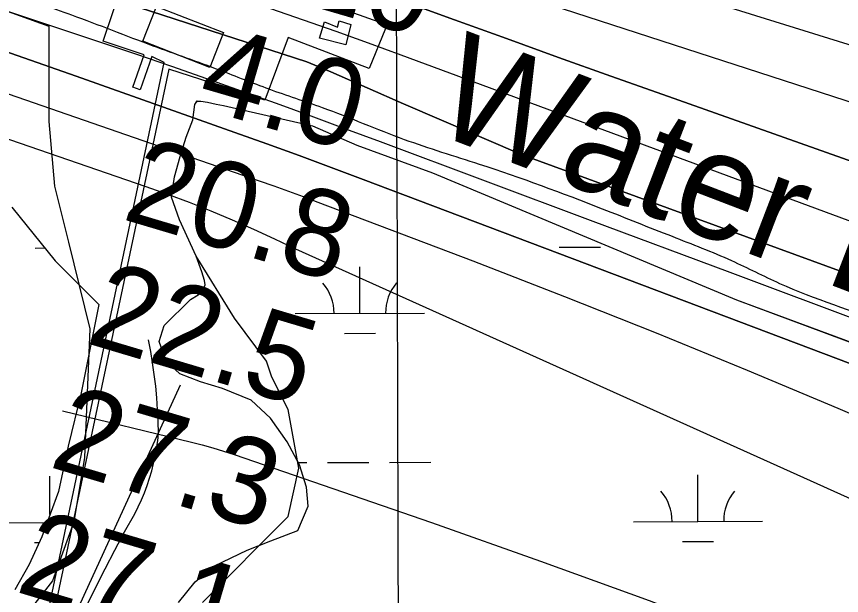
# Model space of a CAD drawing. Extents: x 3361039 to 3398939, y 576572 to 602007.
# Drawn here: x 3391205 to 3391844, y 584508 to 584956 of the extents above; entities that cross this region are included whole.
import ezdxf

# ---------------------------------------------------------------- set-up
doc = ezdxf.new("R2010")
doc.units = 0
for name, color, linetype in [('V-BLDG-OTLN', 7, 'Continuous'), ('V-CHAN-DOCK', 7, 'Continuous'), ('V-GRID-MAJR', 7, 'Continuous'), ('V-RIVR-EDGE', 7, 'Continuous'), ('V-RIVR-IDEN', 7, 'Continuous'), ('V-RIVR-RANG', 7, 'Continuous'), ('V-ROAD-CNTR', 7, 'Continuous'), ('V-SITE-VEGE', 7, 'Continuous'), ('V-TOPO-DPTH', 7, 'Continuous'), ('V-TOPO-MAJR', 7, 'Continuous'), ('V-TOPO-MINR', 7, 'Continuous'), ('V-TOPO-WATR', 7, 'Continuous'), ('V-WETL-SWMP', 7, 'Continuous')]:
    doc.layers.add(name, color=color, linetype=linetype)

msp = doc.modelspace()

# ---------------------------------------------------------------- linework, layer by layer
at = {"layer": 'V-BLDG-OTLN'}
for points in [[(3391313.48, 584963.85), (3391365.34, 584943.77), (3391354.9, 584916.81), (3391302.75, 584937)], [(3391439.85, 584939.35), (3391443.51, 584951.96), (3391453.76, 584948.03), (3391454.84, 584952.87), (3391463.93, 584949.99), (3391460.09, 584934.15)]]:
    msp.add_lwpolyline(points, close=True, dxfattribs=at)
at = {"layer": 'V-CHAN-DOCK'}
msp.add_lwpolyline([(3391216.09, 584431.75), (3391319.37, 584920.56), (3391309.86, 584925.21), (3391300.77, 584899.42), (3391295.21, 584901.54), (3391303.99, 584926.45), (3391272.04, 584937.06), (3391287.95, 584983.96), (3391295.12, 584980.8), (3391307.68, 585015.67), (3391489.23, 584950.77), (3391490.81, 584946.78), (3391478.14, 584915.88), (3391415.45, 584939.89), (3391397.31, 584891.39), (3391322.99, 584915.37), (3391227.75, 584465.31), (3391220.49, 584430.82), (3391216.09, 584431.75)], dxfattribs=at)
at = {"layer": 'V-GRID-MAJR'}
msp.add_spline([(3391508.24, 582029.76), (3391489.73, 588088.95), (3391471.22, 594150.08), (3391452.71, 600211.22), (3391452.7, 600213.13)], degree=3, dxfattribs=at)
at = {"layer": 'V-RIVR-EDGE'}
msp.add_spline([(3387368.61, 585771.04), (3387388.99, 585767.6), (3387407.26, 585766.09), (3387418.22, 585761.68), (3387425.51, 585756.54), (3387441.59, 585752.85), (3387452.55, 585751.36), (3387462.06, 585753.9), (3387477.43, 585758.24), (3387482.91, 585759.33), (3387491.69, 585759.31), (3387502.28, 585758.18), (3387510.32, 585756.34), (3387521.64, 585753.02), (3387530.05, 585752.27), (3387538.46, 585752.24), (3387549.79, 585752.22), (3387558.94, 585755.48), (3387571.37, 585756.92), (3387583.43, 585757.25), (3387598.42, 585756.12), (3387629.84, 585749.46), (3387659.8, 585743.54), (3387703.28, 585736.85), (3387727.4, 585734.23), (3387739.1, 585733.47), (3387750.8, 585734.17), (3387753.72, 585731.61), (3387763.2, 585723.91), (3387774.52, 585720.59), (3387790.61, 585719.82), (3387800.12, 585721.62), (3387814, 585720.13), (3387824.6, 585720.1), (3387847.25, 585714.2), (3387884.16, 585709.35), (3387930.2, 585702.66), (3387980.65, 585701.07), (3388035.1, 585696.55), (3388076.04, 585694.62), (3388096.87, 585693.84), (3388120.26, 585690.49), (3388145.1, 585685.31), (3388171.78, 585682.32), (3388198.82, 585676.77), (3388222.56, 585669.4), (3388245.57, 585660.57), (3388260.91, 585655.42), (3388279.55, 585655.37), (3388291.26, 585658.26), (3388298.95, 585663.73), (3388299.32, 585666.29), (3388298.96, 585670.67), (3388290.56, 585674.35), (3388291.67, 585677.27), (3388293.86, 585678.36), (3388303, 585677.61), (3388318.72, 585676.47), (3388334.06, 585672.78), (3388354.14, 585663.59), (3388357.06, 585659.93), (3388363.27, 585658.09), (3388368.39, 585658.07), (3388370.95, 585660.99), (3388375.34, 585662.08), (3388379, 585661.34), (3388383.01, 585659.13), (3388383.73, 585654.38), (3388384.08, 585649.26), (3388389.93, 585647.42), (3388406, 585642.26), (3388468.86, 585637.72), (3388491.52, 585635.84), (3388534.64, 585628.42), (3388578.12, 585619.17), (3388610.64, 585613.61), (3388635.85, 585612.08), (3388727.94, 585599.43), (3388768.5, 585591.65), (3388822.57, 585580.92), (3388864.95, 585570.58), (3388906.6, 585562.8), (3388924.14, 585559.46), (3388938.77, 585561.99), (3388961.44, 585563.39), (3388974.22, 585560.07), (3389007.47, 585553.41), (3389018.81, 585554.48), (3389027.22, 585555.92), (3389037.09, 585555.89), (3389051.7, 585553.67), (3389061.21, 585553.28), (3389081.31, 585552.13), (3389098.12, 585550.99), (3389120.42, 585548.74), (3389143.44, 585546.49), (3389160.24, 585542.06), (3389200.8, 585534.65), (3389222.35, 585525.1), (3389247.19, 585519.19), (3389280.43, 585509.6), (3389307.45, 585497.83), (3389334.48, 585487.17), (3389349.45, 585483.11), (3389361.52, 585483.08), (3389382.71, 585479.01), (3389396.96, 585476.78), (3389416.68, 585468.69), (3389441.88, 585458.39), (3389464.89, 585451.39), (3389479.5, 585449.16), (3389506.18, 585446.17), (3389533.23, 585447.2), (3389558.45, 585444.21), (3389577.81, 585437.95), (3389603.38, 585431.3), (3389618.72, 585425.05), (3389639.16, 585415.13), (3389657.8, 585410.33), (3389693.24, 585404.76), (3389768.86, 585383.01), (3389806.48, 585373.05), (3389854.34, 585362.33), (3389881.75, 585358.6), (3389913.91, 585354.5), (3389953.74, 585349.29), (3390008.19, 585341.84), (3390037.78, 585336.28), (3390074.32, 585327.79), (3390128.02, 585312.67), (3390164.54, 585301.61), (3390200.7, 585289.82), (3390292.74, 585255.6), (3390327.06, 585241.26), (3390360.67, 585231.67), (3390404.51, 585220.96), (3390454.94, 585214.26), (3390483.08, 585210.53), (3390491.85, 585209.41), (3390494.4, 585207.21), (3390501.33, 585200.98), (3390507.91, 585200.6), (3390527.27, 585196.17), (3390545.91, 585195.02), (3390557.61, 585194.26), (3390574.41, 585189.83), (3390605.46, 585179.52), (3390698.6, 585148.22), (3390763.25, 585126.86), (3390811.09, 585111.02), (3390852.37, 585097.76), (3390900.95, 585081.56), (3390948.06, 585063.53), (3390993.71, 585048.43), (3391036.81, 585031.87), (3391070.77, 585020.09), (3391140.54, 584997.62), (3391201.53, 584974.07), (3391247.54, 584957.51), (3391310.73, 584933.59), (3391362.22, 584914.82), (3391400.57, 584900.1), (3391441.84, 584885.75), (3391505.38, 584861.1), (3391563.46, 584841.95), (3391658.78, 584807.35), (3391712.83, 584786.01), (3391758.84, 584767.26), (3391796.08, 584749.62), (3391880.45, 584718.34), (3391926.83, 584701.41), (3391969.2, 584685.22), (3392003.88, 584666.85), (3392040.03, 584650.32), (3392077.64, 584635.97), (3392135.71, 584613.16), (3392164.91, 584598.1), (3392195.95, 584583.77), (3392224.82, 584578.21), (3392263.54, 584567.88), (3392290.57, 584559.77), (3392322.7, 584546.53), (3392396.46, 584512.72), (3392439.92, 584496.16), (3392471.69, 584484.75), (3392502.01, 584473.34), (3392510.77, 584467.47), (3392535.24, 584458.27), (3392606.09, 584432.88), (3392632.38, 584421.48), (3392666.71, 584406.77), (3392715.64, 584386.91), (3392777.36, 584364.83), (3392827.04, 584348.25), (3392863.56, 584335.37), (3392897.89, 584321.76), (3392928.56, 584307.79), (3392965.45, 584294.91), (3393010.01, 584279.08), (3393054.56, 584263.25), (3393092.54, 584248.53), (3393195.16, 584206.61), (3393234.23, 584187.87), (3393264.53, 584173.54), (3393294.11, 584162.13), (3393336.85, 584147.4), (3393374.47, 584136.34), (3393402.23, 584127.5), (3393414.27, 584119.8), (3393435.45, 584109.14), (3393459.18, 584098.12), (3393478.9, 584087.47), (3393513.6, 584076.42), (3393541.72, 584067.21), (3393588.1, 584047.35), (3393643.25, 584028.94), (3393668.44, 584018.28), (3393699.85, 584005.04), (3393737.1, 583991.79), (3393781.66, 583975.96), (3393884.66, 583943.17), (3393927.03, 583928.81), (3393981.08, 583908.2), (3394043.9, 583885.38), (3394095.77, 583868.08), (3394154.93, 583847.09), (3394200.22, 583830.53), (3394246.97, 583816.16), (3394293, 583801.42), (3394349.61, 583781.18), (3394409.13, 583754.71), (3394451.84, 583730.48), (3394470.45, 583720.2), (3394481.77, 583715.42), (3394494.2, 583713.56), (3394502.59, 583708.06), (3394507.32, 583700.37), (3394511.34, 583697.8), (3394522.66, 583692.29), (3394557.34, 583675.75), (3394600.44, 583659.93), (3394658.14, 583638.95), (3394704.53, 583623.48), (3394760.42, 583607.62), (3394823.98, 583588.82), (3394867.8, 583570.8), (3394925.86, 583546.9), (3394972.24, 583528.87), (3394995.62, 583520.04), (3395064.67, 583504.15), (3395088.42, 583499.34), (3395120.2, 583491.59), (3395149.05, 583480.55), (3395173.17, 583476.83), (3395201.3, 583471.28), (3395236.37, 583459.86), (3395256.82, 583451.77), (3395280.93, 583445.5), (3395300.3, 583445.08), (3395316.74, 583440.65), (3395324.4, 583433.32), (3395335.35, 583425.99), (3395353.6, 583417.9), (3395398.9, 583403.9), (3395426.3, 583397.25), (3395442, 583391), (3395455.87, 583383.28), (3395475.96, 583377.75), (3395495.68, 583369.3), (3395511.03, 583368.16), (3395530.4, 583365.92), (3395550.49, 583361.85), (3395654.61, 583334.91), (3395704.66, 583322.35), (3395743.73, 583306.9), (3395765.27, 583295.52), (3395788.28, 583286.32), (3395816.41, 583278.94), (3395861.72, 583270.79), (3395916.16, 583261.52), (3395960.74, 583252.63), (3396008.6, 583242.64), (3396060.84, 583230.45), (3396093.36, 583222.33), (3396135.36, 583208.7), (3396170.06, 583199.84), (3396204.41, 583191.35), (3396254.82, 583177.33), (3396301.21, 583165.89), (3396364.42, 583152.94), (3396399.13, 583144.44), (3396426.89, 583138.53), (3396463.07, 583132.95), (3396489.75, 583132.89), (3396523.38, 583130.24), (3396607.78, 583113.95), (3396670.26, 583102.1), (3396708.26, 583095.43), (3396742.97, 583089.49), (3396775.14, 583083.89)], degree=3, dxfattribs=at)
at = {"layer": 'V-ROAD-CNTR'}
for points in [[(3391259.23, 584499.82), (3391266.34, 584514.3), (3391273.64, 584528.68), (3391281.11, 584542.96), (3391288.78, 584557.15), (3391296.62, 584571.24), (3391299.3, 584576.55), (3391301.79, 584581.96), (3391304.08, 584587.45), (3391306.17, 584593.02), (3391308.05, 584598.66), (3391309.73, 584604.36), (3391311.21, 584610.13), (3391312.48, 584615.94), (3391313.53, 584621.79), (3391314.37, 584627.68), (3391315, 584633.59), (3391314.79, 584642.69), (3391314.36, 584651.78), (3391313.71, 584660.85), (3391312.85, 584669.91), (3391311.77, 584678.94), (3391310.47, 584687.95), (3391308.96, 584696.92), (3391307.23, 584705.86)], [(3391105.77, 584199.79), (3391198.24, 584379.28), (3391332.08, 584670.96)]]:
    msp.add_lwpolyline(points, dxfattribs=at)
at = {"layer": 'V-SITE-VEGE'}
for p, q in [((3391343.18, 584887.97), (3391344.92, 584890.78)), ((3391344.92, 584890.78), (3391347.89, 584890.62)), ((3391347.89, 584890.62), (3391352.85, 584889.97)), ((3391352.85, 584889.97), (3391359.6, 584888.32)), ((3391341.56, 584876.31), (3391343.18, 584887.97)), ((3391359.6, 584888.32), (3391365.3, 584887.41)), ((3391365.3, 584887.41), (3391375.51, 584884.97)), ((3391375.51, 584884.97), (3391434.23, 584871.52)), ((3391336.5, 584862.69), (3391341.56, 584876.31)), ((3391434.23, 584871.52), (3391468.65, 584856.58)), ((3391331.68, 584847.76), (3391336.5, 584862.69)), ((3391468.65, 584856.58), (3391527.38, 584835.2)), ((3391327.44, 584831.99), (3391331.68, 584847.76)), ((3391527.38, 584835.2), (3391762.8, 584736.93)), ((3391325.19, 584816.31), (3391327.44, 584831.99)), ((3391331.32, 584798.82), (3391325.19, 584816.31)), ((3391344.21, 584770.77), (3391331.32, 584798.82)), ((3391373.86, 584722.63), (3391344.21, 584770.77)), ((3391762.8, 584736.93), (3391959.52, 584663.64)), ((3391398.75, 584689.43), (3391373.86, 584722.63)), ((3391402.9, 584676.97), (3391398.75, 584689.43)), ((3391415.34, 584652.06), (3391402.9, 584676.97)), ((3391423.64, 584606.4), (3391415.34, 584652.06)), ((3391415.34, 584569.04), (3391423.64, 584606.4)), ((3391348.97, 584502.61), (3391415.34, 584569.04))]:
    msp.add_line(p, q, dxfattribs=at)
msp.add_lwpolyline([(3391127.99, 584985.74), (3391230.13, 584948.79), (3391230.13, 584874.88), (3391234.47, 584824.88), (3391245.34, 584781.41), (3391261.86, 584714.33), (3391257.71, 584614.7), (3391249.42, 584564.89), (3391232.82, 584519.22), (3391203.79, 584481.86)], dxfattribs=at)
at = {"layer": 'V-TOPO-DPTH'}
for points in [[(3390678.68, 585282.14), (3390852.22, 585234.68), (3390949.88, 585207.56), (3391047.4, 585179.91), (3391144.68, 585151.49), (3391241.82, 585122.55), (3391423.59, 585067.59), (3391453.42, 585058.52), (3391483.22, 585049.38), (3391512.99, 585040.14), (3391542.75, 585030.83), (3391694.3, 584983.11), (3391799.86, 584950.05), (3391905.48, 584917.2), (3392011.21, 584884.69), (3392117.01, 584852.38), (3392327.21, 584788.55), (3392352.54, 584780.89), (3392377.87, 584773.24), (3392403.21, 584765.64), (3392428.56, 584758.07), (3392783.55, 584652.29), (3392834.95, 584637), (3392886.36, 584621.74)], [(3390678.68, 585282.14), (3390852.22, 585234.68), (3390949.88, 585207.56), (3391047.4, 585179.91), (3391144.68, 585151.49), (3391241.82, 585122.55), (3391423.59, 585067.59), (3391453.42, 585058.52), (3391483.22, 585049.38), (3391512.99, 585040.14), (3391542.75, 585030.83), (3391694.3, 584983.11), (3391799.86, 584950.05), (3391905.48, 584917.2), (3392011.21, 584884.69), (3392117.01, 584852.38), (3392327.21, 584788.55), (3392352.54, 584780.89), (3392377.87, 584773.24), (3392403.21, 584765.64), (3392428.56, 584758.07), (3392783.55, 584652.29), (3392834.95, 584637), (3392886.36, 584621.74)], [(3393031.47, 584404.12), (3392383, 584655.56), (3392365.1, 584662.05), (3392347.18, 584668.51), (3392329.25, 584674.92), (3392311.3, 584681.3), (3391705.74, 584895.71), (3391665.33, 584910.08), (3391624.94, 584924.53), (3391584.59, 584939.09), (3391544.27, 584953.73), (3391492.33, 584972.68), (3391477.98, 584977.85), (3391463.61, 584982.94), (3391449.2, 584987.93), (3391434.77, 584992.85), (3391420.29, 584997.64), (3391405.79, 585002.33), (3391391.23, 585006.88), (3391376.65, 585011.32), (3390699.4, 585214.13), (3390668.65, 585223.2)], [(3390668.65, 585223.2), (3390699.4, 585214.13), (3391376.65, 585011.32), (3391391.23, 585006.88), (3391405.79, 585002.33), (3391420.29, 584997.64), (3391434.77, 584992.85), (3391449.2, 584987.93), (3391463.61, 584982.94), (3391477.98, 584977.85), (3391492.33, 584972.68), (3391544.27, 584953.73), (3391584.59, 584939.09), (3391624.94, 584924.53), (3391665.33, 584910.08), (3391705.74, 584895.71), (3392311.3, 584681.3), (3392329.25, 584674.92), (3392347.18, 584668.51), (3392365.1, 584662.05), (3392383, 584655.56), (3393031.47, 584404.12)], [(3392928.64, 584331.59), (3392676.04, 584440.35), (3392339.21, 584576.56), (3392323.05, 584583.41), (3392305.19, 584590.26), (3391596.6, 584849.14), (3391504.75, 584888.53), (3391448.62, 584913.36), (3391429.91, 584921.07), (3391160.22, 585008.58), (3390745.08, 585150.09), (3390651.51, 585182.68)], [(3390651.51, 585182.68), (3390745.08, 585150.09), (3391160.22, 585008.58), (3391429.91, 584921.07), (3391448.62, 584913.36), (3391504.75, 584888.53), (3391596.6, 584849.14), (3392305.19, 584590.26), (3392323.05, 584583.41), (3392339.21, 584576.56), (3392676.04, 584440.35), (3392928.64, 584331.59)], [(3392986.66, 584240.65), (3392333.62, 584495.22), (3392300.45, 584508.97), (3392267.28, 584522.7), (3392234.1, 584536.42), (3392180.19, 584558.7), (3392119.94, 584583.28), (3392059.55, 584607.49), (3391998.94, 584631.14), (3391938.19, 584654.43), (3391473.68, 584830.06), (3391448.83, 584839.36), (3391423.95, 584848.55), (3391399, 584857.59), (3391374.02, 584866.51), (3391251.26, 584909.91), (3391164.74, 584940.09), (3391078.06, 584969.79), (3390991.13, 584998.77), (3390904.05, 585027.26), (3390649.76, 585109.28)]]:
    msp.add_lwpolyline(points, dxfattribs=at)
at = {"layer": 'V-TOPO-MAJR'}
msp.add_lwpolyline([(3391240.56, 584650.94), (3391340.55, 584626.71), (3391348.89, 584624.56), (3391357.2, 584622.26), (3391365.43, 584619.72), (3391373.62, 584617.03), (3391526.6, 584564.37), (3391611.01, 584534.59), (3391695.09, 584503.96), (3391778.7, 584472.05), (3391862, 584439.28), (3392196.65, 584304.67), (3392216.24, 584296.6), (3392235.75, 584288.32), (3392255.12, 584279.73), (3392274.4, 584270.93), (3392353.62, 584233.98), (3392377.35, 584222.39), (3392400.8, 584210.25), (3392423.79, 584197.29), (3392446.49, 584183.78), (3392458.11, 584176.09)], dxfattribs=at)
at = {"layer": 'V-TOPO-MINR'}
for points in [[(3390678.68, 585282.14), (3390852.22, 585234.68), (3390949.88, 585207.56), (3391047.4, 585179.91), (3391144.68, 585151.49), (3391241.82, 585122.55), (3391423.59, 585067.59), (3391453.42, 585058.52), (3391483.22, 585049.38), (3391512.99, 585040.14), (3391542.75, 585030.83), (3391694.3, 584983.11), (3391799.86, 584950.05), (3391905.48, 584917.2), (3392011.21, 584884.69), (3392117.01, 584852.38), (3392327.21, 584788.55), (3392352.54, 584780.89), (3392377.87, 584773.24), (3392403.21, 584765.64), (3392428.56, 584758.07), (3392783.55, 584652.29), (3392834.95, 584637), (3392886.36, 584621.74)], [(3390656.01, 585264.91), (3391449.41, 585019.99), (3391460.93, 585016.41), (3391472.43, 585012.8), (3391483.92, 585009.14), (3391495.39, 585005.44), (3392170.03, 584786.77), (3392202.26, 584776.27), (3392234.47, 584765.71), (3392266.65, 584755.06), (3392298.81, 584744.35), (3392358, 584724.53), (3392360.55, 584723.68), (3392363.1, 584722.83), (3392365.65, 584721.97), (3392368.2, 584721.12), (3392655.39, 584625.04), (3392725.16, 584601.76), (3392794.96, 584578.58), (3392864.81, 584555.51)], [(3390668.65, 585223.2), (3390699.4, 585214.13), (3391376.65, 585011.32), (3391391.23, 585006.88), (3391405.79, 585002.33), (3391420.29, 584997.64), (3391434.77, 584992.85), (3391449.2, 584987.93), (3391463.61, 584982.94), (3391477.98, 584977.85), (3391492.33, 584972.68), (3391544.27, 584953.73), (3391584.59, 584939.09), (3391624.94, 584924.53), (3391665.33, 584910.08), (3391705.74, 584895.71), (3392311.3, 584681.3), (3392329.25, 584674.92), (3392347.18, 584668.51), (3392365.1, 584662.05), (3392383, 584655.56), (3393031.47, 584404.12)], [(3390668.48, 585197.97), (3390896.04, 585128.73), (3390989.33, 585099.82), (3391082.4, 585070.25), (3391175.15, 585039.71), (3391267.7, 585008.51), (3391401.86, 584962.51), (3391427.13, 584953.74), (3391452.37, 584944.86), (3391477.53, 584935.79), (3391502.66, 584926.6), (3392077.3, 584714.19), (3392119.9, 584698.41), (3392162.49, 584682.6), (3392205.05, 584666.75), (3392247.6, 584650.85), (3392251.72, 584649.31), (3392292.19, 584634.12), (3392332.63, 584618.86), (3392373.03, 584603.49), (3392413.4, 584588.07), (3393024.79, 584355.28)], [(3390691.29, 585129.56), (3391270.75, 584936.12), (3391297.9, 584926.96), (3391325.02, 584917.68), (3391352.08, 584908.24), (3391379.09, 584898.69), (3391406.06, 584888.99), (3391433, 584879.22), (3391459.9, 584869.33), (3391486.77, 584859.36), (3391649.49, 584798.61), (3391757.69, 584758.2), (3391865.89, 584717.77)], [(3390649.76, 585109.28), (3390904.05, 585027.26), (3390991.13, 584998.77), (3391078.06, 584969.79), (3391164.74, 584940.09), (3391251.26, 584909.91), (3391374.02, 584866.51), (3391399, 584857.59), (3391423.95, 584848.55), (3391448.83, 584839.36), (3391473.68, 584830.06), (3391938.19, 584654.43), (3391998.94, 584631.14), (3392059.55, 584607.49), (3392119.94, 584583.28), (3392180.19, 584558.7), (3392234.1, 584536.42), (3392267.28, 584522.7), (3392300.45, 584508.97), (3392333.62, 584495.22), (3392986.66, 584240.65)], [(3390617.24, 585092.88), (3390711.53, 585062.51), (3390770.43, 585043.33), (3390829.25, 585023.88), (3390887.93, 585004.03), (3390946.53, 584983.93), (3391393.03, 584829.05), (3391404.43, 584825.03), (3391415.81, 584820.96), (3391427.16, 584816.78), (3391438.48, 584812.54), (3391558.47, 584767.01), (3391629.59, 584739.51), (3391700.47, 584711.42), (3391770.99, 584682.45), (3391841.27, 584652.89), (3392226.21, 584488.13), (3392256.54, 584475.3), (3393034.35, 584188.93)], [(3390612.83, 585063.35), (3391305.14, 584824.7), (3391322.05, 584818.65), (3391338.86, 584812.35), (3391355.52, 584805.66), (3391372.08, 584798.71), (3391388.51, 584791.45), (3391404.86, 584784.02), (3391421.09, 584776.34), (3392242.13, 584407), (3392267.57, 584396.72), (3392293, 584386.42), (3392910.01, 584097.13)]]:
    msp.add_lwpolyline(points, dxfattribs=at)
at = {"layer": 'V-TOPO-WATR'}
msp.add_lwpolyline([(3392928.64, 584331.59), (3392676.04, 584440.35), (3392339.21, 584576.56), (3392323.05, 584583.41), (3392305.19, 584590.26), (3391596.6, 584849.14), (3391504.75, 584888.53), (3391448.62, 584913.36), (3391429.91, 584921.07), (3391160.22, 585008.58), (3390745.08, 585150.09), (3390651.51, 585182.68)], dxfattribs=at)
at = {"layer": 'V-WETL-SWMP'}
for p, q in [((3391343.17, 584887.97), (3391344.92, 584890.77)), ((3391344.92, 584890.77), (3391347.89, 584890.62)), ((3391347.89, 584890.62), (3391352.85, 584889.97)), ((3391352.85, 584889.97), (3391359.6, 584888.32)), ((3391341.56, 584876.31), (3391343.17, 584887.97)), ((3391359.6, 584888.32), (3391365.3, 584887.4)), ((3391365.3, 584887.4), (3391375.51, 584884.96)), ((3391375.51, 584884.96), (3391434.23, 584871.52)), ((3391336.5, 584862.69), (3391341.56, 584876.31)), ((3391434.23, 584871.52), (3391468.65, 584856.58)), ((3391331.68, 584847.76), (3391336.5, 584862.69)), ((3391468.65, 584856.58), (3391527.38, 584835.2)), ((3391327.44, 584831.99), (3391331.68, 584847.76)), ((3391527.38, 584835.2), (3391762.8, 584736.92)), ((3391325.19, 584816.31), (3391327.44, 584831.99)), ((3391331.32, 584798.82), (3391325.19, 584816.31)), ((3391339.84, 584780.17), (3391331.32, 584798.82)), ((3391219.4, 584776.97), (3391226.91, 584776.99)), ((3391344.21, 584770.78), (3391339.84, 584780.17)), ((3391625.41, 584777.54), (3391657.41, 584777.63)), ((3391348.57, 584758.54), (3391344.21, 584770.78)), ((3391470.96, 584726.37), (3391470.86, 584762.37)), ((3391350.72, 584751.69), (3391348.57, 584758.54)), ((3391351.2, 584748.44), (3391350.72, 584751.69)), ((3391345.83, 584740.64), (3391348.93, 584743.17)), ((3391348.93, 584743.17), (3391351.2, 584748.44)), ((3391319.3, 584717.06), (3391339.81, 584737.12)), ((3391339.81, 584737.12), (3391345.83, 584740.64)), ((3391762.8, 584736.92), (3391959.52, 584663.64)), ((3391420.96, 584726.23), (3391520.96, 584726.51)), ((3391315.63, 584704.47), (3391319.3, 584717.06)), ((3391459, 584710.91), (3391483, 584710.97)), ((3391320.99, 584689.44), (3391315.63, 584704.47)), ((3391331.54, 584679.48), (3391320.99, 584689.44)), ((3391347.64, 584673.4), (3391331.54, 584679.48)), ((3391364.54, 584668.11), (3391347.64, 584673.4)), ((3391386.92, 584659.21), (3391364.54, 584668.11)), ((3391401.77, 584645.26), (3391386.92, 584659.21)), ((3391414.59, 584626.99), (3391401.77, 584645.26)), ((3391424.27, 584609.14), (3391414.59, 584626.99)), ((3391423.36, 584610.81), (3391429.87, 584610.83)), ((3391429.61, 584591.74), (3391424.27, 584609.14)), ((3391445.87, 584610.87), (3391477.87, 584610.96)), ((3391493.87, 584611.01), (3391525.87, 584611.09)), ((3391230.84, 584570.53), (3391230.75, 584600.41)), ((3391732.84, 584565.24), (3391732.74, 584601.24)), ((3391431.04, 584577.14), (3391429.61, 584591.74)), ((3391422.97, 584558.3), (3391431.04, 584577.14)), ((3391180.86, 584564.28), (3391228.56, 584564.41)), ((3391682.85, 584565.1), (3391782.84, 584565.37)), ((3391401.99, 584550.23), (3391422.97, 584558.3)), ((3391218.9, 584548.95), (3391222.49, 584548.96)), ((3391383.78, 584542.93), (3391401.99, 584550.23)), ((3391720.89, 584549.77), (3391744.89, 584549.84)), ((3391358.43, 584530.96), (3391383.78, 584542.93)), ((3391343.33, 584518.49), (3391358.43, 584530.96)), ((3391330.55, 584502.46), (3391343.33, 584518.49))]:
    msp.add_line(p, q, dxfattribs=at)
msp.add_lwpolyline([(3391201.4, 584808.46), (3391234.89, 584767.12), (3391268.9, 584733.21), (3391262.27, 584700.95), (3391255.21, 584664.75), (3391244.94, 584623.45), (3391237.49, 584588.44), (3391224.52, 584553.48), (3391214.84, 584531.9), (3391203.61, 584512.3)], dxfattribs=at)
for centre, start, end in [((3391415.72, 584726.69), 359.3865, 40.93016), ((3391526.2, 584727), 139.38645, 180.93011), ((3391677.6, 584565.56), 359.3865, 40.93016), ((3391788.09, 584565.86), 139.38645, 180.93011)]:
    msp.add_arc(centre, 35.25, start, end, dxfattribs=at)

# ---------------------------------------------------------------- texts
at = {"layer": 'V-RIVR-IDEN'}
msp.add_text('Water Edge', height=83, rotation=339.05005, dxfattribs=at).set_placement((3391523.54, 584867.92))
at = {"layer": 'V-RIVR-RANG'}
for s, rotation, p in [('-10', 343.70203, (3391393.44, 584975.96)), ('4.0', 343.70203, (3391343.12, 584886.48)), ('20.8', 343.41833, (3391285.71, 584799.7)), ('22.5', 343.41833, (3391257.41, 584703.78)), ('27.3', 343.41833, (3391229.11, 584607.87)), ('27.1', 343.41833, (3391203.08, 584511.28))]:
    msp.add_text(s, height=67, rotation=rotation, dxfattribs=at).set_placement(p)

doc.saveas('drawing.dxf')
